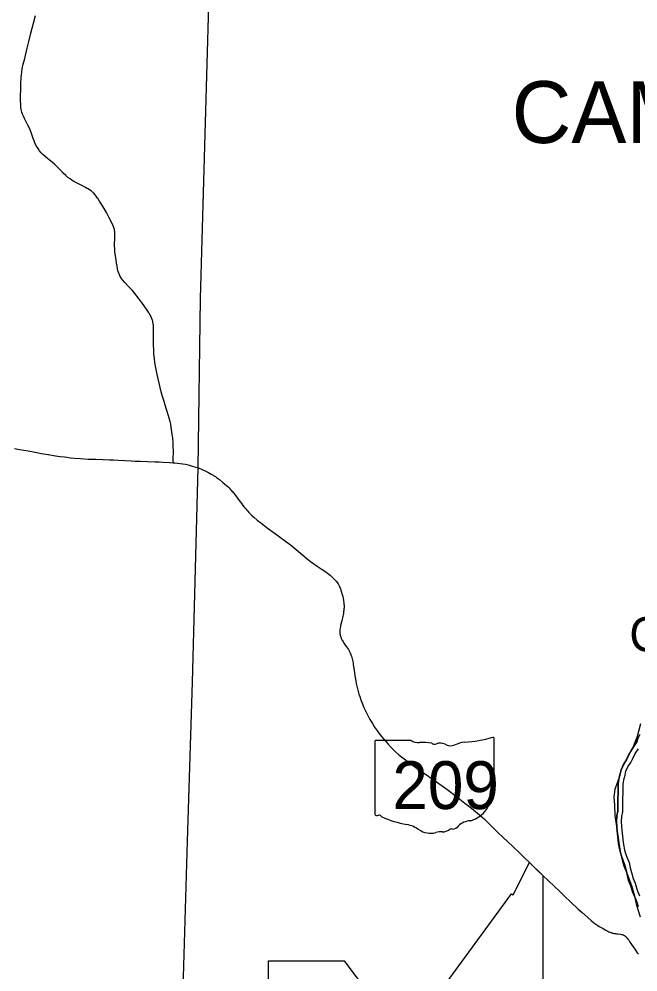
# Model space of a CAD drawing. Extents: x -29.6 to 34, y 0 to 22.
# Drawn here: x -26.883 to -25.281, y 3.151 to 5.614 of the extents above; entities that cross this region are included whole.
import ezdxf

# ---------------------------------------------------------------- set-up
doc = ezdxf.new("R2010")
doc.units = 0
for name, color, linetype in [('GM_X_Corporation', 7, 'Continuous'), ('GM_X_Corporation_Text', 7, 'Continuous'), ('GM_X_Major_River', 7, 'Continuous'), ('GM_X_State_Location', 7, 'Continuous'), ('GM_X_State_Route', 7, 'Continuous'), ('GM_X_State_Shield', 7, 'Continuous'), ('GM_X_Township', 7, 'Continuous'), ('GM_X_Township_Text', 7, 'Continuous')]:
    doc.layers.add(name, color=color, linetype=linetype)

msp = doc.modelspace()

# ---------------------------------------------------------------- linework, layer by layer
at = {"layer": 'GM_X_Corporation'}
for points in [[(-25.2746, 3.2921), (-25.2845, 3.3227), (-25.2899, 3.3471), (-25.2975, 3.3731), (-25.3097, 3.4052), (-25.3181, 3.4258), (-25.3258, 3.4579), (-25.3303, 3.4854), (-25.336, 3.5268), (-25.3401, 3.5543), (-25.3415, 3.5825), (-25.3428, 3.6031), (-25.3401, 3.6244), (-25.3332, 3.6423), (-25.3277, 3.6594), (-25.3243, 3.6739), (-25.3167, 3.691), (-25.3057, 3.7116), (-25.2927, 3.7341), (-25.2827, 3.7602), (-25.2741, 3.7929)], [(-25.8626, 3.0065), (-25.6085, 3.3526), (-25.6041, 3.3501), (-25.5618, 3.4335), (-25.5274, 3.4005), (-25.5272, 3.1251)], [(-26.2378, 3.017), (-26.2378, 3.1793), (-26.0416, 3.1793), (-25.9755, 3.0911)]]:
    msp.add_lwpolyline(points, dxfattribs=at)
at = {"layer": 'GM_X_Major_River'}
for points in [[(-25.2813, 3.3204), (-25.2847, 3.3308), (-25.2884, 3.3421), (-25.295, 3.3565), (-25.3005, 3.3751), (-25.3056, 3.3873), (-25.3098, 3.4035), (-25.3132, 3.4166), (-25.3152, 3.4267), (-25.321, 3.4405), (-25.325, 3.4524), (-25.3277, 3.4629), (-25.33, 3.4735), (-25.3316, 3.4839), (-25.3331, 3.5004), (-25.335, 3.5158), (-25.3358, 3.5259), (-25.3371, 3.5393), (-25.336, 3.5542), (-25.3339, 3.5662), (-25.3334, 3.5748), (-25.3338, 3.5844), (-25.3335, 3.6004), (-25.3326, 3.6134), (-25.3326, 3.6252), (-25.3323, 3.6381), (-25.3297, 3.6532), (-25.3276, 3.6627), (-25.3253, 3.6737), (-25.3189, 3.6875), (-25.3107, 3.6991), (-25.3064, 3.708), (-25.3, 3.7216), (-25.2909, 3.7351), (-25.2847, 3.7454), (-25.2815, 3.7543), (-25.2769, 3.7644)], [(-25.2769, 3.7644), (-25.2815, 3.7543), (-25.2847, 3.7454), (-25.2909, 3.7351), (-25.3, 3.7216), (-25.3064, 3.708), (-25.3107, 3.6991), (-25.3189, 3.6875), (-25.3253, 3.6737), (-25.3276, 3.6627), (-25.3297, 3.6532), (-25.3323, 3.6381), (-25.3326, 3.6252), (-25.3326, 3.6134), (-25.3335, 3.6004), (-25.3338, 3.5844), (-25.3334, 3.5748), (-25.3339, 3.5662), (-25.336, 3.5542), (-25.3371, 3.5393), (-25.3358, 3.5259), (-25.335, 3.5158), (-25.3331, 3.5004), (-25.3316, 3.4839), (-25.33, 3.4735), (-25.3277, 3.4629), (-25.325, 3.4524), (-25.321, 3.4405), (-25.3152, 3.4267), (-25.3132, 3.4166), (-25.3098, 3.4035), (-25.3056, 3.3873), (-25.3005, 3.3751), (-25.295, 3.3565), (-25.2884, 3.3421), (-25.2847, 3.3308), (-25.2813, 3.3204)], [(-25.2762, 3.3469), (-25.2827, 3.3611), (-25.2882, 3.3795), (-25.2932, 3.3915), (-25.2972, 3.4068), (-25.3005, 3.4195), (-25.3027, 3.4305), (-25.3088, 3.4451), (-25.3124, 3.456), (-25.315, 3.466), (-25.3172, 3.4759), (-25.3186, 3.4855), (-25.3202, 3.5018), (-25.322, 3.5171), (-25.3228, 3.527), (-25.324, 3.5394), (-25.323, 3.5526), (-25.3209, 3.5647), (-25.3203, 3.5746), (-25.3207, 3.5846), (-25.3205, 3.5999), (-25.3195, 3.613), (-25.3196, 3.6251), (-25.3193, 3.6368), (-25.3169, 3.6507), (-25.3149, 3.6599), (-25.3128, 3.6695), (-25.3076, 3.6809), (-25.2995, 3.6924), (-25.2946, 3.7023), (-25.2887, 3.7152), (-25.2799, 3.728)]]:
    msp.add_lwpolyline(points, dxfattribs=at)
at = {"layer": 'GM_X_State_Route'}
for points in [[(-26.4838, 4.4672), (-26.4838, 4.4707), (-26.4837, 4.481), (-26.4836, 4.4913), (-26.4836, 4.5005), (-26.4838, 4.5068), (-26.4845, 4.5187), (-26.4853, 4.5309), (-26.4865, 4.5415), (-26.4881, 4.5537), (-26.4889, 4.5589), (-26.4905, 4.5667), (-26.4921, 4.5738), (-26.4969, 4.591), (-26.4997, 4.6), (-26.5022, 4.6076), (-26.5076, 4.626), (-26.5123, 4.6411), (-26.5159, 4.6545), (-26.5198, 4.6695), (-26.5233, 4.6845), (-26.5257, 4.6959), (-26.5288, 4.7126), (-26.5311, 4.7265), (-26.5325, 4.7369), (-26.5337, 4.7479), (-26.5345, 4.7591), (-26.5349, 4.7716), (-26.5349, 4.7914), (-26.5347, 4.8008), (-26.5349, 4.8141), (-26.5354, 4.8235), (-26.5358, 4.8263), (-26.5364, 4.83), (-26.5371, 4.8333), (-26.5375, 4.8349), (-26.5387, 4.838), (-26.541, 4.844), (-26.5423, 4.8467), (-26.5436, 4.8494), (-26.5459, 4.8534), (-26.548, 4.8567), (-26.5531, 4.8644), (-26.5632, 4.8788), (-26.5734, 4.8929), (-26.5833, 4.9051), (-26.5897, 4.9124), (-26.6021, 4.9256), (-26.6094, 4.9333), (-26.6149, 4.9401), (-26.6177, 4.9439), (-26.621, 4.9491), (-26.624, 4.9554), (-26.625, 4.9579), (-26.6262, 4.9615), (-26.6271, 4.9645), (-26.628, 4.9686), (-26.6293, 4.9757), (-26.6306, 4.9835), (-26.6317, 4.9909), (-26.632, 4.9932), (-26.6338, 5.0066), (-26.6348, 5.0144), (-26.6354, 5.0214), (-26.6357, 5.0277), (-26.6355, 5.0352), (-26.6352, 5.0443), (-26.6346, 5.0552), (-26.6348, 5.0612), (-26.6351, 5.0643), (-26.6355, 5.0672), (-26.636, 5.0702), (-26.6366, 5.0727), (-26.6376, 5.0758), (-26.6387, 5.0791), (-26.6398, 5.0819), (-26.6424, 5.0873), (-26.6503, 5.1021), (-26.6569, 5.1139), (-26.6656, 5.1286), (-26.6747, 5.1436), (-26.6783, 5.1495), (-26.6798, 5.1516), (-26.6836, 5.1569), (-26.6856, 5.1596), (-26.6894, 5.1642), (-26.6911, 5.1657), (-26.6925, 5.1669), (-26.694, 5.1681), (-26.6966, 5.1701), (-26.7005, 5.1728), (-26.7107, 5.1788), (-26.7205, 5.1841), (-26.734, 5.191), (-26.7411, 5.1947), (-26.7451, 5.1971), (-26.7466, 5.198), (-26.7509, 5.201), (-26.7563, 5.2052), (-26.762, 5.2101), (-26.7683, 5.216), (-26.7759, 5.2239), (-26.7843, 5.2328), (-26.7901, 5.2385), (-26.7961, 5.2437), (-26.8092, 5.254), (-26.814, 5.2579), (-26.8157, 5.2593), (-26.8209, 5.264), (-26.8257, 5.2689), (-26.8298, 5.2738), (-26.8337, 5.2795), (-26.8375, 5.2857), (-26.8408, 5.292), (-26.8441, 5.2995), (-26.8465, 5.3055), (-26.8484, 5.3108), (-26.8518, 5.3211), (-26.8544, 5.328), (-26.8567, 5.3338), (-26.8599, 5.3403), (-26.8689, 5.3574), (-26.8715, 5.3632), (-26.8738, 5.3686), (-26.8756, 5.3739), (-26.8772, 5.3803), (-26.878, 5.3865), (-26.8785, 5.3933), (-26.8788, 5.4034), (-26.8788, 5.4172), (-26.8784, 5.4313), (-26.878, 5.4482), (-26.8774, 5.4621), (-26.8768, 5.4702), (-26.876, 5.4771), (-26.8747, 5.4857), (-26.8722, 5.4975), (-26.8683, 5.5129), (-26.8621, 5.5388), (-26.8578, 5.5568), (-26.8527, 5.5776), (-26.8457, 5.6038), (-26.8407, 5.6237)], [(-26.8946, 4.5042), (-26.8814, 4.5019), (-26.8596, 4.4981), (-26.8412, 4.4948), (-26.8247, 4.4916), (-26.808, 4.4886), (-26.8063, 4.4883), (-26.7884, 4.4854), (-26.7769, 4.4838), (-26.7654, 4.4823), (-26.7596, 4.4816), (-26.7497, 4.4804), (-26.7393, 4.4793), (-26.7242, 4.4781), (-26.7038, 4.477), (-26.684, 4.4764), (-26.6655, 4.4758), (-26.6492, 4.475), (-26.6381, 4.4745), (-26.6271, 4.4739), (-26.609, 4.4731), (-26.5927, 4.4723), (-26.5823, 4.4718), (-26.5764, 4.4716), (-26.5684, 4.4713), (-26.5501, 4.4707), (-26.5317, 4.4699), (-26.5207, 4.4695), (-26.5108, 4.4691), (-26.4934, 4.468), (-26.4838, 4.4672), (-26.48, 4.4669), (-26.4592, 4.4645), (-26.4523, 4.4634), (-26.445, 4.4618), (-26.4372, 4.4597), (-26.4255, 4.456), (-26.4193, 4.4539)], [(-26.4193, 4.4539), (-26.4167, 4.453), (-26.4092, 4.45), (-26.4013, 4.4463), (-26.3941, 4.4426), (-26.3859, 4.4382), (-26.3749, 4.4314), (-26.3717, 4.4289), (-26.3644, 4.4236), (-26.3561, 4.4171), (-26.3503, 4.4123), (-26.3463, 4.4088), (-26.343, 4.4057), (-26.3395, 4.4023), (-26.3365, 4.3992), (-26.3341, 4.3966), (-26.3319, 4.3941), (-26.3299, 4.3918), (-26.3278, 4.3891), (-26.3246, 4.3849), (-26.3108, 4.3665), (-26.3068, 4.3611), (-26.3034, 4.3567), (-26.3001, 4.3525), (-26.297, 4.3488), (-26.2936, 4.3448), (-26.2909, 4.3418), (-26.288, 4.3388), (-26.2856, 4.3363), (-26.2827, 4.3334), (-26.2794, 4.3303), (-26.2755, 4.3266), (-26.2665, 4.319), (-26.2574, 4.3117), (-26.2449, 4.3022), (-26.2377, 4.2967), (-26.231, 4.2918), (-26.2194, 4.2836), (-26.2026, 4.2717), (-26.1873, 4.2605), (-26.1758, 4.2517), (-26.1655, 4.2432), (-26.1489, 4.2285), (-26.1374, 4.2186), (-26.1332, 4.2153), (-26.1286, 4.2119), (-26.1204, 4.2063), (-26.1112, 4.2001), (-26.101, 4.1933), (-26.0891, 4.1849), (-26.085, 4.1818), (-26.0782, 4.1764), (-26.0751, 4.1737), (-26.0717, 4.1706), (-26.0667, 4.1657), (-26.0647, 4.1636), (-26.0625, 4.161), (-26.059, 4.1565), (-26.0572, 4.1539), (-26.0556, 4.1512), (-26.0543, 4.1489), (-26.0533, 4.1468), (-26.0521, 4.144), (-26.051, 4.1411), (-26.05, 4.1383), (-26.049, 4.1349), (-26.0467, 4.1266), (-26.0455, 4.1214), (-26.0443, 4.1163), (-26.0435, 4.1118), (-26.043, 4.1092), (-26.0426, 4.106), (-26.0423, 4.1036), (-26.0421, 4.1015), (-26.042, 4.0991), (-26.0418, 4.0959), (-26.0419, 4.0922), (-26.0421, 4.0894), (-26.0425, 4.0855), (-26.043, 4.0823), (-26.0437, 4.0778), (-26.0453, 4.0703), (-26.0481, 4.0586), (-26.0495, 4.0526), (-26.0508, 4.0467), (-26.0515, 4.043), (-26.0521, 4.0392), (-26.0525, 4.0366), (-26.0527, 4.0345), (-26.0528, 4.0324), (-26.0528, 4.0305), (-26.0528, 4.0291), (-26.0527, 4.0273), (-26.0526, 4.0263), (-26.0525, 4.0252), (-26.0523, 4.024), (-26.0521, 4.0227), (-26.0517, 4.0208), (-26.0512, 4.0187), (-26.0504, 4.016), (-26.0498, 4.0143), (-26.0492, 4.0128), (-26.0484, 4.011), (-26.0478, 4.0098), (-26.047, 4.0084), (-26.0454, 4.0059), (-26.0414, 3.9999), (-26.0387, 3.9961), (-26.0353, 3.9913), (-26.033, 3.9878), (-26.0308, 3.9844), (-26.0291, 3.9813), (-26.0282, 3.9797), (-26.0272, 3.9777), (-26.0263, 3.9757), (-26.0253, 3.9734), (-26.0243, 3.9708), (-26.023, 3.9673), (-26.0219, 3.9637), (-26.0209, 3.9603), (-26.02, 3.9568), (-26.0193, 3.9532), (-26.0187, 3.9498), (-26.0181, 3.9464), (-26.0164, 3.9352), (-26.0149, 3.9244), (-26.0137, 3.9164), (-26.0116, 3.9038), (-26.0103, 3.8969), (-26.008, 3.8866), (-26.0053, 3.8759), (-26.0034, 3.8693), (-26.0015, 3.863), (-25.9987, 3.8547), (-25.9952, 3.8454), (-25.9907, 3.8346), (-25.9858, 3.824), (-25.9808, 3.814), (-25.9752, 3.8038), (-25.9686, 3.7928), (-25.9629, 3.7839), (-25.9557, 3.7733), (-25.949, 3.7645), (-25.9401, 3.7535), (-25.928, 3.7399), (-25.9197, 3.7308), (-25.9147, 3.7258), (-25.9097, 3.721), (-25.9001, 3.7124), (-25.8865, 3.7014), (-25.8754, 3.6929), (-25.8563, 3.6796), (-25.8334, 3.6636), (-25.8091, 3.6465), (-25.7764, 3.6232), (-25.7514, 3.6043), (-25.7292, 3.5873), (-25.7122, 3.5741), (-25.6915, 3.5573), (-25.6793, 3.5466), (-25.6687, 3.5366), (-25.6445, 3.5123), (-25.6304, 3.4984), (-25.6061, 3.4758), (-25.5879, 3.4586)], [(-25.5879, 3.4586), (-25.575, 3.4461), (-25.5616, 3.433)], [(-25.5616, 3.433), (-25.541, 3.413), (-25.5272, 3.4)], [(-25.5272, 3.4), (-25.5131, 3.3866), (-25.5125, 3.3861), (-25.4835, 3.3586), (-25.472, 3.3477), (-25.4358, 3.3131), (-25.4258, 3.3041), (-25.4114, 3.2913), (-25.4026, 3.2837), (-25.3961, 3.2787), (-25.3953, 3.2781), (-25.3852, 3.2709), (-25.3816, 3.2685), (-25.3769, 3.2656), (-25.3718, 3.2627), (-25.3649, 3.2588), (-25.3596, 3.256), (-25.3568, 3.2549), (-25.3545, 3.2538), (-25.3528, 3.253), (-25.3509, 3.2524), (-25.3491, 3.2518), (-25.3475, 3.2514), (-25.3458, 3.251), (-25.344, 3.2506), (-25.342, 3.2503), (-25.3398, 3.2499), (-25.3373, 3.2496), (-25.3339, 3.2492), (-25.3265, 3.2483), (-25.3242, 3.248), (-25.3227, 3.2477), (-25.3213, 3.2473), (-25.3199, 3.2468), (-25.3186, 3.2461), (-25.3174, 3.2454), (-25.3161, 3.2446), (-25.3148, 3.2436), (-25.3134, 3.2426), (-25.312, 3.2412), (-25.3107, 3.2397), (-25.3092, 3.2379), (-25.3073, 3.2353), (-25.3053, 3.2326), (-25.3017, 3.2273), (-25.2982, 3.222), (-25.294, 3.2158), (-25.2878, 3.2067), (-25.2832, 3.2005), (-25.2801, 3.1964)]]:
    msp.add_lwpolyline(points, dxfattribs=at)
at = {"layer": 'GM_X_State_Shield'}
for p, q in [((-25.9624, 3.7464), (-25.9624, 3.5588)), ((-25.8689, 3.7496), (-25.9594, 3.7496)), ((-25.6534, 3.6561), (-25.6534, 3.7543)), ((-25.6534, 3.6561), (-25.6534, 3.6561))]:
    msp.add_line(p, q, dxfattribs=at)
for centre, major_axis, start_param, end_param in [((-25.9589, 3.7468), (0.00358, 0), 1.712693, 3.28349), ((-25.8473, 3.7714), (0.0347, 0), 4.042523, 4.731795), ((-25.7635, 4.0054), (0.3277, 0), 4.814394, 5.042369), ((-25.6568, 3.7547), (0.00344, 0), 6.141152, 7.989035), ((-25.8358, 3.6443), (0.1246, 0), 1.404758, 1.657858), ((-25.8075, 3.7478), (0.01, 0), 3.836095, 5.185415), ((-25.7928, 3.7261), (0.0208, 0), 0.950623, 2.079405), ((-25.7659, 3.7558), (0.0251, 0), 4.081561, 5.145723), ((-25.7217, 3.6923), (0.0659, 0), 1.699011, 2.107814), ((-25.6542, 3.6489), (0.00532, 0), 1.883978, 3.671073), ((-25.6881, 3.6365), (0.032, 0), 5.934695, 6.695948), ((-25.6571, 3.6557), (0.00368, 0), 5.05454, 6.418171), ((-25.6411, 3.6151), (0.0232, 0), 2.387724, 3.262537), ((-25.7451, 3.6026), (0.082, 0), 5.101752, 6.440018), ((-25.9588, 3.5584), (0.00361, 0), 3.00124, 4.508301), ((-25.9583, 3.5776), (0.0276, 0), 4.665946, 4.897461), ((-25.9526, 3.548), (0.00994, 0), 0.519207, 1.627899), ((-25.8272, 3.7165), (0.2366, 0), 4.195997, 4.488961), ((-25.8977, 3.4745), (0.074, 0), 0.823519, 1.323587), ((-25.7674, 3.5406), (0.0265, 0), 4.937069, 5.64225), ((-25.7106, 3.5061), (0.0449, 0), 1.647645, 2.488434), ((-25.8177, 3.547), (0.047, 0), 4.026481, 4.996735), ((-25.7905, 3.4822), (0.0386, 0), 1.495662, 1.94098), ((-25.7871, 3.533), (0.025, 0), 4.691044, 5.507374), ((-25.7644, 3.5148), (0.00705, 0), 1.147584, 2.315152)]:
    msp.add_ellipse(centre, major_axis=major_axis, ratio=0.8, start_param=start_param, end_param=end_param, dxfattribs=at)
at = {"layer": 'GM_X_Township'}
msp.add_lwpolyline([(-26.5174, 1.0528), (-26.5025, 1.5759), (-26.4941, 1.8989), (-26.4937, 1.919), (-26.4843, 2.2228), (-26.4828, 2.2798), (-26.4776, 2.4606), (-26.4717, 2.6621), (-26.4646, 2.9029), (-26.4469, 3.4885), (-26.434, 3.9004), (-26.4195, 4.4544), (-26.4135, 4.8923), (-26.3873, 5.8027)], dxfattribs=at)

# ---------------------------------------------------------------- texts
at = {"layer": 'GM_X_Corporation_Text'}
msp.add_text('CAMBRIDGE', height=0.08878, rotation=0, dxfattribs=at).set_placement((-25.3037, 3.9796))
at = {"layer": 'GM_X_State_Location'}
msp.add_text('209', height=0.000178, rotation=0, dxfattribs=at).set_placement((-25.8741, 3.6272))
for s in ['s', 'r']:
    msp.add_text(s, height=0.000178, dxfattribs=at).set_placement((-25.8114, 3.6401))
at = {"layer": 'GM_X_State_Shield'}
msp.add_text('209', height=0.1236, dxfattribs=at).set_placement((-25.917, 3.572))
at = {"layer": 'GM_X_Township_Text'}
msp.add_text('CAMBRIDGE', height=0.1598, rotation=0, dxfattribs=at).set_placement((-25.6082, 5.294))

doc.saveas('drawing.dxf')
